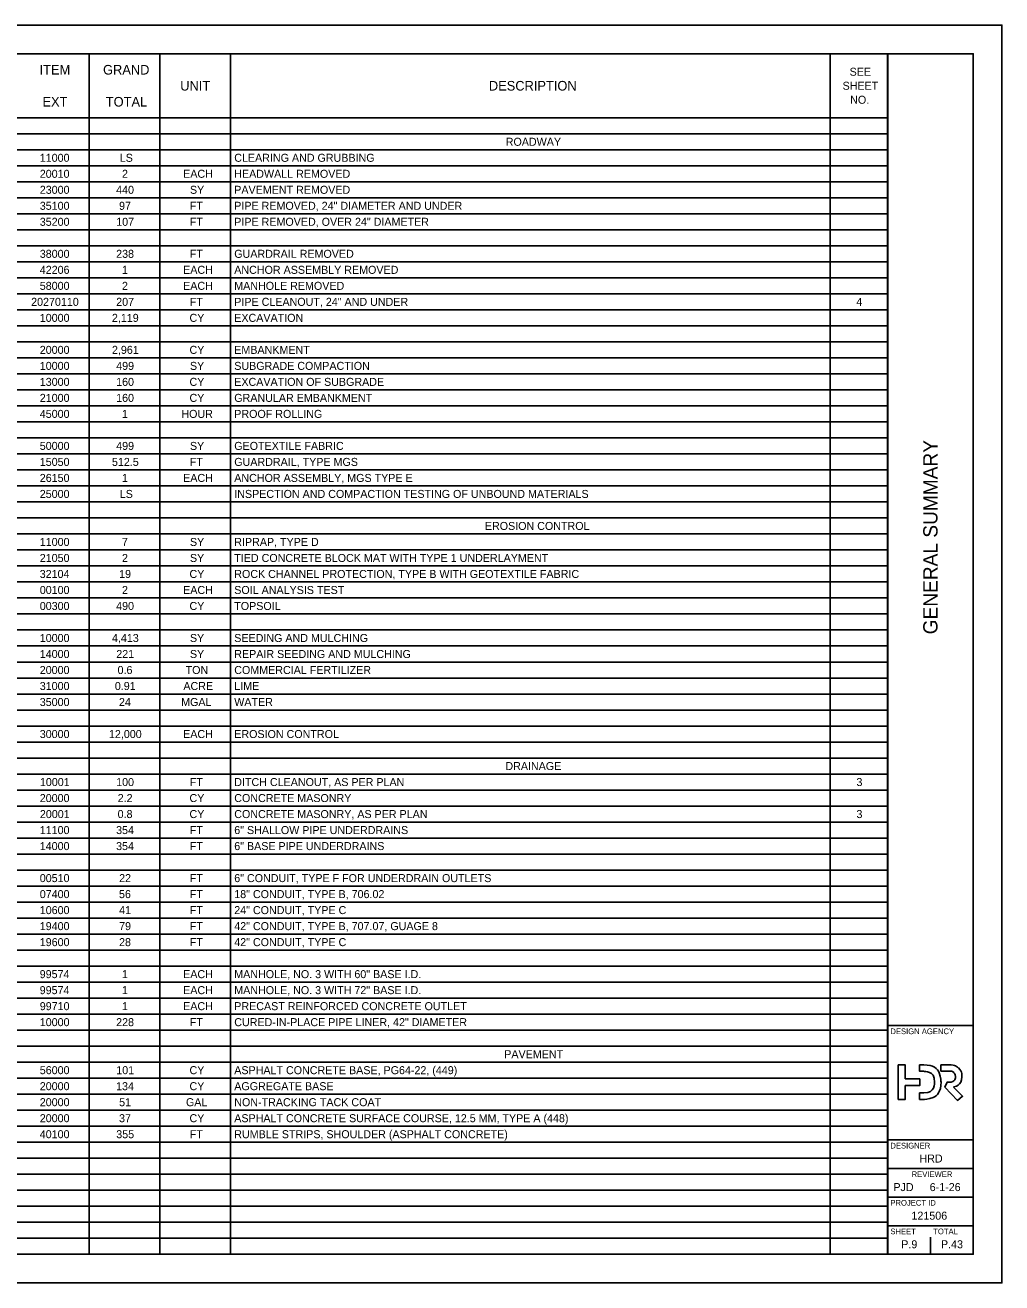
# Model space of a CAD drawing. Extents: x 0 to 34, y 0 to 22.
# Drawn here: x 16.92 to 34, y 0 to 22 of the extents above; entities that cross this region are included whole.
import ezdxf

# ---------------------------------------------------------------- set-up
doc = ezdxf.new("R2010")
doc.units = 0
for name, color, linetype in [('SH_Border', 7, 'Continuous'), ('SH_Cut_Line', 7, 'Continuous'), ('SH_Data', 7, 'Continuous'), ('SH_Text', 7, 'Continuous')]:
    doc.layers.add(name, color=color, linetype=linetype)

msp = doc.modelspace()

# ---------------------------------------------------------------- linework, layer by layer
at = {"layer": 'SH_Border'}
for p, q in [((32, 0.5), (32, 21.5)), ((32, 4.5), (33.5, 4.5)), ((32, 2.5), (33.5, 2.5)), ((32, 2), (33.5, 2)), ((32, 1.5), (33.5, 1.5)), ((32, 1), (33.5, 1))]:
    msp.add_line(p, q, dxfattribs=at)
msp.add_lwpolyline([(1.5, 21.5), (33.5, 21.5), (33.5, 0.5), (1.5, 0.5)], close=True, dxfattribs=at)
at = {"layer": 'SH_Cut_Line'}
msp.add_lwpolyline([(0, 0), (34, 0), (34, 22), (0, 22)], close=True, dxfattribs=at)
at = {"layer": 'SH_Data'}
for p, q in [((1.5, 21.5), (32.004, 21.5)), ((18.036, 21.5), (18.036, 0.5)), ((19.272, 21.5), (19.272, 0.5)), ((20.507, 21.5), (20.507, 0.5)), ((30.999, 21.5), (30.999, 0.5)), ((32.004, 21.5), (32.004, 0.5)), ((1.5, 20.38), (32.004, 20.38)), ((1.5, 20.1), (32.004, 20.1)), ((1.5, 19.82), (32.004, 19.82)), ((1.5, 19.54), (32.004, 19.54)), ((1.5, 19.26), (32.004, 19.26)), ((1.5, 18.98), (32.004, 18.98)), ((1.5, 18.7), (32.004, 18.7)), ((1.5, 18.42), (32.004, 18.42)), ((1.5, 18.14), (32.004, 18.14)), ((1.5, 17.86), (32.004, 17.86)), ((1.5, 17.58), (32.004, 17.58)), ((1.5, 17.3), (32.004, 17.3)), ((1.5, 17.02), (32.004, 17.02)), ((1.5, 16.74), (32.004, 16.74)), ((1.5, 16.46), (32.004, 16.46)), ((1.5, 16.18), (32.004, 16.18)), ((1.5, 15.9), (32.004, 15.9)), ((1.5, 15.62), (32.004, 15.62)), ((1.5, 15.34), (32.004, 15.34)), ((1.5, 15.06), (32.004, 15.06)), ((1.5, 14.78), (32.004, 14.78)), ((1.5, 14.5), (32.004, 14.5)), ((1.5, 14.22), (32.004, 14.22)), ((1.5, 13.94), (32.004, 13.94)), ((1.5, 13.66), (32.004, 13.66)), ((1.5, 13.38), (32.004, 13.38)), ((1.5, 13.1), (32.004, 13.1)), ((1.5, 12.82), (32.004, 12.82)), ((1.5, 12.54), (32.004, 12.54)), ((1.5, 12.26), (32.004, 12.26)), ((1.5, 11.98), (32.004, 11.98)), ((1.5, 11.7), (32.004, 11.7)), ((1.5, 11.42), (32.004, 11.42)), ((1.5, 11.14), (32.004, 11.14)), ((1.5, 10.86), (32.004, 10.86)), ((1.5, 10.58), (32.004, 10.58)), ((1.5, 10.3), (32.004, 10.3)), ((1.5, 10.02), (32.004, 10.02)), ((1.5, 9.74), (32.004, 9.74)), ((1.5, 9.46), (32.004, 9.46)), ((1.5, 9.18), (32.004, 9.18)), ((1.5, 8.9), (32.004, 8.9)), ((1.5, 8.62), (32.004, 8.62)), ((1.5, 8.34), (32.004, 8.34)), ((1.5, 8.06), (32.004, 8.06)), ((1.5, 7.78), (32.004, 7.78)), ((1.5, 7.5), (32.004, 7.5)), ((1.5, 7.22), (32.004, 7.22)), ((1.5, 6.94), (32.004, 6.94)), ((1.5, 6.66), (32.004, 6.66)), ((1.5, 6.38), (32.004, 6.38)), ((1.5, 6.1), (32.004, 6.1)), ((1.5, 5.82), (32.004, 5.82)), ((1.5, 5.54), (32.004, 5.54)), ((1.5, 5.26), (32.004, 5.26)), ((1.5, 4.98), (32.004, 4.98)), ((1.5, 4.7), (32.004, 4.7)), ((1.5, 4.42), (32.004, 4.42)), ((1.5, 4.14), (32.004, 4.14)), ((1.5, 3.86), (32.004, 3.86)), ((1.5, 3.58), (32.004, 3.58)), ((32.75, 3.5), (32.75, 3.5)), ((1.5, 3.3), (32.004, 3.3)), ((1.5, 3.02), (32.004, 3.02)), ((1.5, 2.74), (32.004, 2.74)), ((1.5, 2.46), (32.004, 2.46)), ((1.5, 2.18), (32.004, 2.18)), ((1.5, 1.9), (32.004, 1.9)), ((1.5, 1.62), (32.004, 1.62)), ((1.5, 1.34), (32.004, 1.34)), ((1.5, 1.06), (32.004, 1.06)), ((1.5, 0.78), (32.004, 0.78)), ((32.375, 0.675), (32.375, 0.675)), ((32.75, 0.5), (32.75, 0.8)), ((1.5, 0.5), (32.004, 0.5))]:
    msp.add_line(p, q, dxfattribs=at)
msp.add_lwpolyline([(32.565, 3.571), (32.311, 3.571), (32.311, 3.813), (32.189, 3.813), (32.189, 3.209), (32.311, 3.209), (32.311, 3.451), (32.565, 3.451)], close=True, dxfattribs=at)
for points in [[(32.634, 3.813), (32.562, 3.813), (32.562, 3.7), (32.634, 3.7)], [(33.063, 3.813), (32.935, 3.813), (32.935, 3.704), (33.072, 3.704)], [(32.634, 3.322), (32.562, 3.322), (32.562, 3.209), (32.634, 3.209)], [(32.936, 3.511), (32.936, 3.511), (32.936, 3.511), (32.936, 3.512), (32.936, 3.512)], [(33.077, 3.51), (33.043, 3.51), (33.003, 3.424), (33.226, 3.192), (33.313, 3.265), (33.155, 3.425)]]:
    msp.add_lwpolyline(points, dxfattribs=at)
for points in [[(32.936, 3.512), (32.936, 3.512), (32.935, 3.686), (32.808, 3.813), (32.634, 3.813)], [(33.239, 3.759), (33.239, 3.759), (33.193, 3.802), (33.141, 3.813), (33.063, 3.813)], [(33.302, 3.605), (33.302, 3.605), (33.302, 3.668), (33.284, 3.716), (33.239, 3.759)], [(32.634, 3.7), (32.634, 3.7), (32.744, 3.7), (32.822, 3.622), (32.822, 3.511)], [(33.072, 3.704), (33.072, 3.704), (33.113, 3.704), (33.141, 3.696), (33.161, 3.676)], [(33.189, 3.607), (33.189, 3.607), (33.189, 3.546), (33.136, 3.51), (33.077, 3.51)], [(33.155, 3.425), (33.155, 3.425), (33.242, 3.441), (33.302, 3.521), (33.302, 3.605)], [(33.161, 3.676), (33.161, 3.676), (33.179, 3.658), (33.189, 3.634), (33.189, 3.607)], [(32.822, 3.511), (32.822, 3.511), (32.822, 3.4), (32.744, 3.322), (32.634, 3.322)], [(32.634, 3.209), (32.634, 3.209), (32.808, 3.209), (32.935, 3.336), (32.936, 3.511)]]:
    msp.add_open_spline(points, degree=3, dxfattribs=at)

# ---------------------------------------------------------------- texts
msp.add_text('GENERAL SUMMARY', height=0.25, rotation=90, dxfattribs=at).set_placement((32.875, 11.344))
for s, height, p in [('DESIGN AGENCY', 0.1, (32.05, 4.35)), ('DESIGNER', 0.1, (32.05, 2.35)), ('HRD', 0.14, (32.559, 2.105)), ('REVIEWER', 0.1, (32.422, 1.85)), ('PJD', 0.14, (32.103, 1.605)), ('6-1-26', 0.14, (32.738, 1.605)), ('PROJECT ID', 0.1, (32.05, 1.35)), ('121506', 0.14, (32.419, 1.105)), ('SHEET', 0.1, (32.05, 0.85)), ('TOTAL', 0.1, (32.8, 0.85)), ('P.9', 0.14, (32.24, 0.605)), ('P.43', 0.14, (32.935, 0.605))]:
    msp.add_text(s, height=height, dxfattribs=at).set_placement(p)
at = {"layer": 'SH_Text'}
for s, height, p in [('ITEM', 0.168, (17.168, 21.136)), ('GRAND', 0.168, (18.278, 21.136)), ('SEE ', 0.14, (31.337, 21.115)), ('UNIT', 0.168, (19.628, 20.856)), ('DESCRIPTION', 0.168, (25.027, 20.856)), ('SHEET ', 0.14, (31.214, 20.87)), ('EXT', 0.168, (17.218, 20.576)), ('TOTAL', 0.168, (18.326, 20.576)), ('NO.', 0.14, (31.347, 20.625)), ('ROADWAY', 0.14, (25.322, 19.89)), ('11000', 0.14, (17.171, 19.61)), ('LS', 0.14, (18.57, 19.61)), ('CLEARING AND GRUBBING', 0.14, (20.573, 19.61)), ('20010', 0.14, (17.171, 19.33)), ('2', 0.14, (18.609, 19.33)), ('EACH', 0.14, (19.679, 19.33)), ('HEADWALL REMOVED', 0.14, (20.573, 19.33)), ('23000', 0.14, (17.171, 19.05)), ('440', 0.14, (18.507, 19.05)), ('SY', 0.14, (19.798, 19.05)), ('PAVEMENT REMOVED', 0.14, (20.573, 19.05)), ('35100', 0.14, (17.171, 18.77)), ('97', 0.14, (18.558, 18.77)), ('FT', 0.14, (19.796, 18.77)), ('PIPE REMOVED, 24" DIAMETER AND UNDER', 0.14, (20.573, 18.77)), ('35200', 0.14, (17.171, 18.49)), ('107', 0.14, (18.508, 18.49)), ('FT', 0.14, (19.796, 18.49)), ('PIPE REMOVED, OVER 24" DIAMETER', 0.14, (20.573, 18.49)), ('38000', 0.14, (17.171, 17.93)), ('238', 0.14, (18.507, 17.93)), ('FT', 0.14, (19.796, 17.93)), ('GUARDRAIL REMOVED', 0.14, (20.573, 17.93)), ('42206', 0.14, (17.171, 17.65)), ('1', 0.14, (18.609, 17.65)), ('EACH', 0.14, (19.679, 17.65)), ('ANCHOR ASSEMBLY REMOVED', 0.14, (20.573, 17.65)), ('58000', 0.14, (17.171, 17.37)), ('2', 0.14, (18.609, 17.37)), ('EACH', 0.14, (19.679, 17.37)), ('MANHOLE REMOVED', 0.14, (20.573, 17.37)), ('20270110', 0.14, (17.02, 17.09)), ('207', 0.14, (18.508, 17.09)), ('FT', 0.14, (19.796, 17.09)), ('PIPE CLEANOUT, 24" AND UNDER', 0.14, (20.573, 17.09)), ('4', 0.14, (31.454, 17.09)), ('10000', 0.14, (17.171, 16.81)), ('2,119', 0.14, (18.433, 16.81)), ('CY', 0.14, (19.79, 16.81)), ('EXCAVATION', 0.14, (20.573, 16.81)), ('20000', 0.14, (17.171, 16.25)), ('2,961', 0.14, (18.434, 16.25)), ('CY', 0.14, (19.79, 16.25)), ('EMBANKMENT', 0.14, (20.573, 16.25)), ('10000', 0.14, (17.171, 15.97)), ('499', 0.14, (18.508, 15.97)), ('SY', 0.14, (19.798, 15.97)), ('SUBGRADE COMPACTION', 0.14, (20.573, 15.97)), ('13000', 0.14, (17.171, 15.69)), ('160', 0.14, (18.507, 15.69)), ('CY', 0.14, (19.79, 15.69)), ('EXCAVATION OF SUBGRADE', 0.14, (20.573, 15.69)), ('21000', 0.14, (17.171, 15.41)), ('160', 0.14, (18.507, 15.41)), ('CY', 0.14, (19.79, 15.41)), ('GRANULAR EMBANKMENT', 0.14, (20.573, 15.41)), ('45000', 0.14, (17.171, 15.13)), ('1', 0.14, (18.609, 15.13)), ('HOUR', 0.14, (19.648, 15.13)), ('PROOF ROLLING', 0.14, (20.573, 15.13)), ('50000', 0.14, (17.171, 14.57)), ('499', 0.14, (18.508, 14.57)), ('SY', 0.14, (19.798, 14.57)), ('GEOTEXTILE FABRIC', 0.14, (20.573, 14.57)), ('15050', 0.14, (17.171, 14.29)), ('512.5', 0.14, (18.434, 14.29)), ('FT', 0.14, (19.796, 14.29)), ('GUARDRAIL, TYPE MGS', 0.14, (20.573, 14.29)), ('26150', 0.14, (17.171, 14.01)), ('1', 0.14, (18.609, 14.01)), ('EACH', 0.14, (19.679, 14.01)), ('ANCHOR ASSEMBLY, MGS TYPE E', 0.14, (20.573, 14.01)), ('25000', 0.14, (17.171, 13.73)), ('LS', 0.14, (18.57, 13.73)), ('INSPECTION AND COMPACTION TESTING OF UNBOUND MATERIALS', 0.14, (20.573, 13.73)), ('EROSION CONTROL', 0.14, (24.957, 13.17)), ('11000', 0.14, (17.171, 12.89)), ('7', 0.14, (18.608, 12.89)), ('SY', 0.14, (19.798, 12.89)), ('RIPRAP, TYPE D', 0.14, (20.573, 12.89)), ('21050', 0.14, (17.171, 12.61)), ('2', 0.14, (18.609, 12.61)), ('SY', 0.14, (19.798, 12.61)), ('TIED CONCRETE BLOCK MAT WITH TYPE 1 UNDERLAYMENT', 0.14, (20.573, 12.61)), ('32104', 0.14, (17.17, 12.33)), ('19', 0.14, (18.559, 12.33)), ('CY', 0.14, (19.79, 12.33)), ('ROCK CHANNEL PROTECTION, TYPE B WITH GEOTEXTILE FABRIC', 0.14, (20.573, 12.33)), ('00100', 0.14, (17.171, 12.05)), ('2', 0.14, (18.609, 12.05)), ('EACH', 0.14, (19.679, 12.05)), ('SOIL ANALYSIS TEST', 0.14, (20.573, 12.05)), ('00300', 0.14, (17.171, 11.77)), ('490', 0.14, (18.507, 11.77)), ('CY', 0.14, (19.79, 11.77)), ('TOPSOIL', 0.14, (20.573, 11.77)), ('10000', 0.14, (17.171, 11.21)), ('4,413', 0.14, (18.434, 11.21)), ('SY', 0.14, (19.798, 11.21)), ('SEEDING AND MULCHING', 0.14, (20.573, 11.21)), ('14000', 0.14, (17.171, 10.93)), ('221', 0.14, (18.509, 10.93)), ('SY', 0.14, (19.798, 10.93)), ('REPAIR SEEDING AND MULCHING', 0.14, (20.573, 10.93)), ('20000', 0.14, (17.171, 10.65)), ('0.6', 0.14, (18.532, 10.65)), ('TON', 0.14, (19.722, 10.65)), ('COMMERCIAL FERTILIZER', 0.14, (20.573, 10.65)), ('31000', 0.14, (17.171, 10.37)), ('0.91', 0.14, (18.484, 10.37)), ('ACRE', 0.14, (19.683, 10.37)), ('LIME', 0.14, (20.573, 10.37)), ('35000', 0.14, (17.171, 10.09)), ('24', 0.14, (18.556, 10.09)), ('MGAL', 0.14, (19.644, 10.09)), ('WATER', 0.14, (20.573, 10.09)), ('30000', 0.14, (17.171, 9.53)), ('12,000', 0.14, (18.381, 9.53)), ('EACH', 0.14, (19.679, 9.53)), ('EROSION CONTROL', 0.14, (20.573, 9.53)), ('DRAINAGE', 0.14, (25.316, 8.97)), ('10001', 0.14, (17.173, 8.69)), ('100', 0.14, (18.507, 8.69)), ('FT', 0.14, (19.796, 8.69)), ('DITCH CLEANOUT, AS PER PLAN', 0.14, (20.573, 8.69)), ('3', 0.14, (31.457, 8.69)), ('20000', 0.14, (17.171, 8.41)), ('2.2', 0.14, (18.534, 8.41)), ('CY', 0.14, (19.79, 8.41)), ('CONCRETE MASONRY', 0.14, (20.573, 8.41)), ('20001', 0.14, (17.173, 8.13)), ('0.8', 0.14, (18.533, 8.13)), ('CY', 0.14, (19.79, 8.13)), ('CONCRETE MASONRY, AS PER PLAN', 0.14, (20.573, 8.13)), ('3', 0.14, (31.457, 8.13)), ('11100', 0.14, (17.171, 7.85)), ('354', 0.14, (18.506, 7.85)), ('FT', 0.14, (19.796, 7.85)), ('6" SHALLOW PIPE UNDERDRAINS', 0.14, (20.573, 7.85)), ('14000', 0.14, (17.171, 7.57)), ('354', 0.14, (18.506, 7.57)), ('FT', 0.14, (19.796, 7.57)), ('6" BASE PIPE UNDERDRAINS', 0.14, (20.573, 7.57)), ('00510', 0.14, (17.171, 7.01)), ('22', 0.14, (18.559, 7.01)), ('FT', 0.14, (19.796, 7.01)), ('6" CONDUIT, TYPE F FOR UNDERDRAIN OUTLETS', 0.14, (20.573, 7.01)), ('07400', 0.14, (17.171, 6.73)), ('56', 0.14, (18.557, 6.73)), ('FT', 0.14, (19.796, 6.73)), ('18" CONDUIT, TYPE B, 706.02', 0.14, (20.573, 6.73)), ('10600', 0.14, (17.171, 6.45)), ('41', 0.14, (18.559, 6.45)), ('FT', 0.14, (19.796, 6.45)), ('24" CONDUIT, TYPE C', 0.14, (20.573, 6.45)), ('19400', 0.14, (17.171, 6.17)), ('79', 0.14, (18.559, 6.17)), ('FT', 0.14, (19.796, 6.17)), ('42" CONDUIT, TYPE B, 707.07, GUAGE 8', 0.14, (20.573, 6.17)), ('19600', 0.14, (17.171, 5.89)), ('28', 0.14, (18.558, 5.89)), ('FT', 0.14, (19.796, 5.89)), ('42" CONDUIT, TYPE C', 0.14, (20.573, 5.89)), ('99574', 0.14, (17.17, 5.33)), ('1', 0.14, (18.609, 5.33)), ('EACH', 0.14, (19.679, 5.33)), ('MANHOLE, NO. 3 WITH 60" BASE I.D.', 0.14, (20.573, 5.33)), ('99574', 0.14, (17.17, 5.05)), ('1', 0.14, (18.609, 5.05)), ('EACH', 0.14, (19.679, 5.05)), ('MANHOLE, NO. 3 WITH 72" BASE I.D.', 0.14, (20.573, 5.05)), ('99710', 0.14, (17.171, 4.77)), ('1', 0.14, (18.609, 4.77)), ('EACH', 0.14, (19.679, 4.77)), ('PRECAST REINFORCED CONCRETE OUTLET', 0.14, (20.573, 4.77)), ('10000', 0.14, (17.171, 4.49)), ('228', 0.14, (18.507, 4.49)), ('FT', 0.14, (19.796, 4.49)), ('CURED-IN-PLACE PIPE LINER, 42" DIAMETER', 0.14, (20.573, 4.49)), ('PAVEMENT', 0.14, (25.296, 3.93)), ('56000', 0.14, (17.171, 3.65)), ('101', 0.14, (18.509, 3.65)), ('CY', 0.14, (19.79, 3.65)), ('ASPHALT CONCRETE BASE, PG64-22, (449)', 0.14, (20.573, 3.65)), ('20000', 0.14, (17.171, 3.37)), ('134', 0.14, (18.506, 3.37)), ('CY', 0.14, (19.79, 3.37)), ('AGGREGATE BASE', 0.14, (20.573, 3.37)), ('20000', 0.14, (17.171, 3.09)), ('51', 0.14, (18.559, 3.09)), ('GAL', 0.14, (19.728, 3.09)), ('NON-TRACKING TACK COAT', 0.14, (20.573, 3.09)), ('20000', 0.14, (17.171, 2.81)), ('37', 0.14, (18.558, 2.81)), ('CY', 0.14, (19.79, 2.81)), ('ASPHALT CONCRETE SURFACE COURSE, 12.5 MM, TYPE A (448)', 0.14, (20.573, 2.81)), ('40100', 0.14, (17.171, 2.53)), ('355', 0.14, (18.509, 2.53)), ('FT', 0.14, (19.796, 2.53)), ('RUMBLE STRIPS, SHOULDER (ASPHALT CONCRETE)', 0.14, (20.573, 2.53))]:
    msp.add_text(s, height=height, dxfattribs=at).set_placement(p)

doc.saveas('drawing.dxf')
